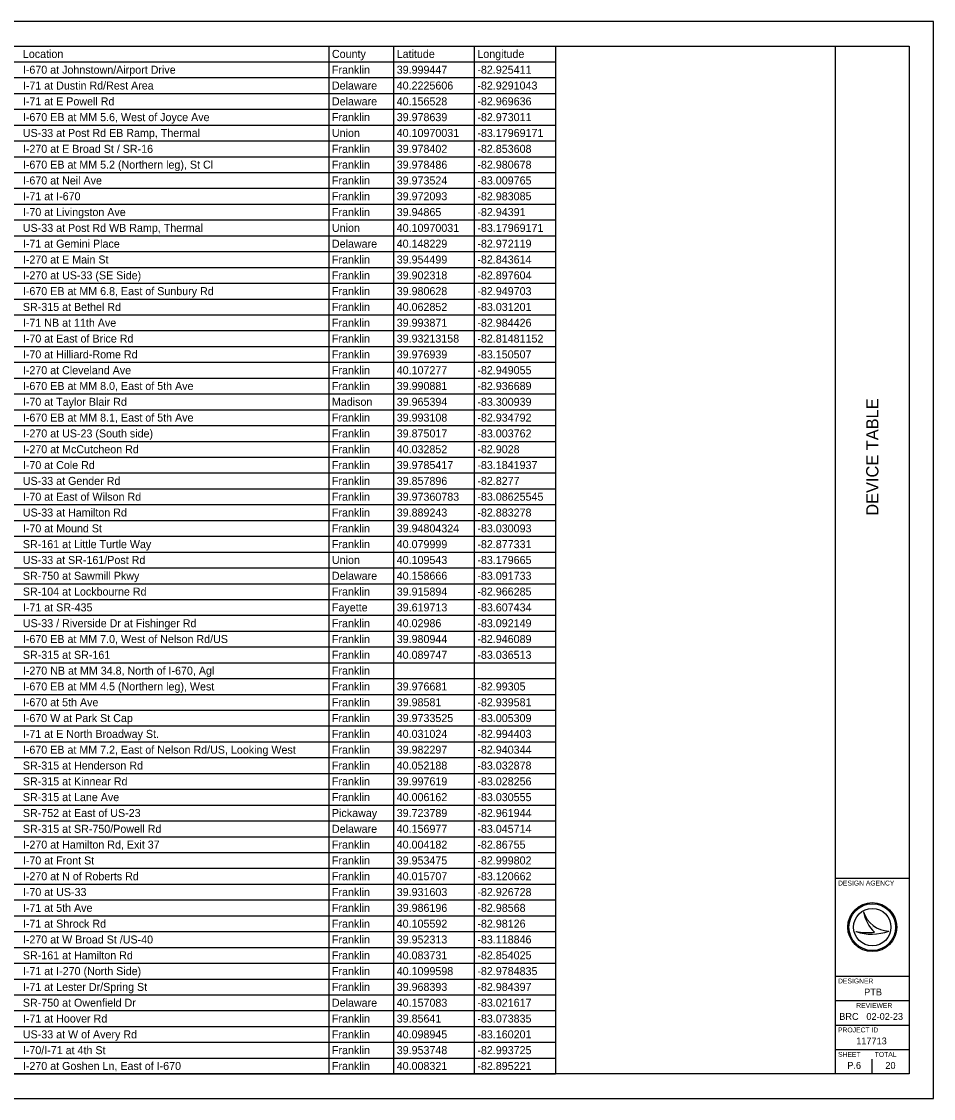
# Model space of a CAD drawing. Extents: x 0 to 34, y 0 to 22.
# Drawn here: x 15.36 to 34, y 0 to 22 of the extents above; entities that cross this region are included whole.
import ezdxf

# ---------------------------------------------------------------- set-up
doc = ezdxf.new("R2010")
doc.units = 0
for name, color, linetype in [('SH_Border', 7, 'Continuous'), ('SH_Cut_Line', 7, 'Continuous'), ('SH_Data', 7, 'Continuous'), ('SH_Text', 7, 'Continuous')]:
    doc.layers.add(name, color=color, linetype=linetype)

msp = doc.modelspace()

# ---------------------------------------------------------------- linework, layer by layer
at = {"layer": 'SH_Border'}
for p, q in [((32, 0.5), (32, 21.5)), ((32, 4.5), (33.5, 4.5)), ((32, 2.5), (33.5, 2.5)), ((32, 2), (33.5, 2)), ((32, 1.5), (33.5, 1.5)), ((32, 1), (33.5, 1))]:
    msp.add_line(p, q, dxfattribs=at)
msp.add_lwpolyline([(1.5, 21.5), (33.5, 21.5), (33.5, 0.5), (1.5, 0.5)], close=True, dxfattribs=at)
at = {"layer": 'SH_Cut_Line'}
msp.add_lwpolyline([(0, 0), (34, 0), (34, 22), (0, 22)], close=True, dxfattribs=at)
at = {"layer": 'SH_Data'}
for p, q in [((32.567, 3.81), (32.567, 3.81)), ((32.417, 3.41), (32.417, 3.41)), ((32.75, 3.5), (32.75, 3.5)), ((33.087, 3.419), (33.087, 3.419)), ((32.375, 0.675), (32.375, 0.675)), ((32.75, 0.5), (32.75, 0.8))]:
    msp.add_line(p, q, dxfattribs=at)
for radius in [0.5, 0.477, 0.477, 0.382]:
    msp.add_circle((32.75, 3.5), radius, dxfattribs=at)
for centre, radius, start, end in [((33.116, 3.998), 0.58, 198.9257, 198.9319), ((33.347, 3.97), 0.796, 191.6379, 191.6421), ((33.116, 3.998), 0.58, 198.9319, 267.1657), ((33.347, 3.97), 0.796, 191.6421, 226.0947), ((32.739, 4.37), 1.013, 251.4576, 290.0832), ((32.648, 4.654), 1.266, 259.4964, 259.4995), ((32.739, 4.37), 1.013, 251.4527, 251.4576), ((32.648, 4.654), 1.266, 259.4995, 276.6672)]:
    msp.add_arc(centre, radius, start, end, dxfattribs=at)
at = {"layer": 'SH_Text'}
for p, q in [((1.5, 21.5), (26.278, 21.5)), ((21.642, 21.5), (21.642, 0.502)), ((22.966, 21.5), (22.966, 0.502)), ((24.614, 21.5), (24.614, 0.502)), ((26.278, 21.5), (26.278, 0.502)), ((1.5, 21.177), (26.278, 21.177)), ((1.5, 20.854), (26.278, 20.854)), ((1.5, 20.531), (26.278, 20.531)), ((1.5, 20.208), (26.278, 20.208)), ((1.5, 19.885), (26.278, 19.885)), ((1.5, 19.562), (26.278, 19.562)), ((1.5, 19.239), (26.278, 19.239)), ((1.5, 18.916), (26.278, 18.916)), ((1.5, 18.593), (26.278, 18.593)), ((1.5, 18.27), (26.278, 18.27)), ((1.5, 17.946), (26.278, 17.946)), ((1.5, 17.623), (26.278, 17.623)), ((1.5, 17.3), (26.278, 17.3)), ((1.5, 16.977), (26.278, 16.977)), ((1.5, 16.654), (26.278, 16.654)), ((1.5, 16.331), (26.278, 16.331)), ((1.5, 16.008), (26.278, 16.008)), ((1.5, 15.685), (26.278, 15.685)), ((1.5, 15.362), (26.278, 15.362)), ((1.5, 15.039), (26.278, 15.039)), ((1.5, 14.716), (26.278, 14.716)), ((1.5, 14.393), (26.278, 14.393)), ((1.5, 14.07), (26.278, 14.07)), ((1.5, 13.747), (26.278, 13.747)), ((1.5, 13.424), (26.278, 13.424)), ((1.5, 13.101), (26.278, 13.101)), ((1.5, 12.778), (26.278, 12.778)), ((1.5, 12.455), (26.278, 12.455)), ((1.5, 12.132), (26.278, 12.132)), ((1.5, 11.809), (26.278, 11.809)), ((1.5, 11.486), (26.278, 11.486)), ((1.5, 11.162), (26.278, 11.162)), ((1.5, 10.839), (26.278, 10.839)), ((1.5, 10.516), (26.278, 10.516)), ((1.5, 10.193), (26.278, 10.193)), ((1.5, 9.87), (26.278, 9.87)), ((1.5, 9.547), (26.278, 9.547)), ((1.5, 9.224), (26.278, 9.224)), ((1.5, 8.901), (26.278, 8.901)), ((1.5, 8.578), (26.278, 8.578)), ((1.5, 8.255), (26.278, 8.255)), ((1.5, 7.932), (26.278, 7.932)), ((1.5, 7.609), (26.278, 7.609)), ((1.5, 7.286), (26.278, 7.286)), ((1.5, 6.963), (26.278, 6.963)), ((1.5, 6.64), (26.278, 6.64)), ((1.5, 6.317), (26.278, 6.317)), ((1.5, 5.994), (26.278, 5.994)), ((1.5, 5.671), (26.278, 5.671)), ((1.5, 5.348), (26.278, 5.348)), ((1.5, 5.025), (26.278, 5.025)), ((1.5, 4.702), (26.278, 4.702)), ((1.5, 4.379), (26.278, 4.379)), ((1.5, 4.055), (26.278, 4.055)), ((1.5, 3.732), (26.278, 3.732)), ((1.5, 3.409), (26.278, 3.409)), ((1.5, 3.086), (26.278, 3.086)), ((1.5, 2.763), (26.278, 2.763)), ((1.5, 2.44), (26.278, 2.44)), ((1.5, 2.117), (26.278, 2.117)), ((1.5, 1.794), (26.278, 1.794)), ((1.5, 1.471), (26.278, 1.471)), ((1.5, 1.148), (26.278, 1.148)), ((1.5, 0.825), (26.278, 0.825)), ((1.5, 0.502), (26.278, 0.502))]:
    msp.add_line(p, q, dxfattribs=at)

# ---------------------------------------------------------------- texts
at = {"layer": 'SH_Data'}
msp.add_text('DEVICE TABLE', height=0.25, rotation=90, dxfattribs=at).set_placement((32.875, 11.905))
for s, height, p in [('DESIGN AGENCY', 0.1, (32.05, 4.35)), ('DESIGNER', 0.1, (32.05, 2.35)), ('PTB', 0.14, (32.584, 2.105)), ('REVIEWER', 0.1, (32.422, 1.85)), ('BRC', 0.14, (32.075, 1.605)), ('02-02-23', 0.14, (32.629, 1.605)), ('PROJECT ID', 0.1, (32.05, 1.35)), ('117713', 0.14, (32.421, 1.105)), ('SHEET', 0.1, (32.05, 0.85)), ('TOTAL', 0.1, (32.8, 0.85)), ('P.6', 0.14, (32.239, 0.605)), ('20', 0.14, (33.017, 0.605))]:
    msp.add_text(s, height=height, dxfattribs=at).set_placement(p)
at = {"layer": 'SH_Text'}
for s, height, p in [('Location', 0.1635, (15.391, 21.257)), ('County', 0.1635, (21.707, 21.257)), ('Latitude', 0.1635, (23.031, 21.257)), ('Longitude', 0.1635, (24.679, 21.257)), ('I-670 at Johnstown/Airport Drive', 0.16346, (15.391, 20.934)), ('Franklin', 0.1635, (21.707, 20.934)), ('39.999447', 0.1635, (23.031, 20.934)), ('-82.925411', 0.1635, (24.679, 20.934)), ('I-71 at Dustin Rd/Rest Area', 0.16346, (15.391, 20.611)), ('Delaware', 0.1635, (21.707, 20.611)), ('40.2225606', 0.1635, (23.031, 20.611)), ('-82.9291043', 0.16346, (24.679, 20.611)), ('I-71 at E Powell Rd', 0.16346, (15.391, 20.288)), ('Delaware', 0.1635, (21.707, 20.288)), ('40.156528', 0.1635, (23.031, 20.288)), ('-82.969636', 0.1635, (24.679, 20.288)), ('I-670 EB at MM 5.6, West of Joyce Ave', 0.16346, (15.391, 19.965)), ('Franklin', 0.1635, (21.707, 19.965)), ('39.978639', 0.1635, (23.031, 19.965)), ('-82.973011', 0.1635, (24.679, 19.965)), ('US-33 at Post Rd EB Ramp, Thermal', 0.16346, (15.391, 19.642)), ('Union', 0.1635, (21.707, 19.642)), ('40.10970031', 0.16346, (23.031, 19.642)), ('-83.17969171', 0.16346, (24.679, 19.642)), ('I-270 at E Broad St / SR-16', 0.16346, (15.391, 19.318)), ('Franklin', 0.1635, (21.707, 19.318)), ('39.978402', 0.1635, (23.031, 19.318)), ('-82.853608', 0.1635, (24.679, 19.318)), ('I-670 EB at MM 5.2 (Northern leg), St Cl', 0.16346, (15.391, 18.995)), ('Franklin', 0.1635, (21.707, 18.995)), ('39.978486', 0.1635, (23.031, 18.995)), ('-82.980678', 0.1635, (24.679, 18.995)), ('I-670 at Neil Ave', 0.16346, (15.391, 18.672)), ('Franklin', 0.1635, (21.707, 18.672)), ('39.973524', 0.1635, (23.031, 18.672)), ('-83.009765', 0.1635, (24.679, 18.672)), ('I-71 at I-670', 0.16346, (15.391, 18.349)), ('Franklin', 0.1635, (21.707, 18.349)), ('39.972093', 0.1635, (23.031, 18.349)), ('-82.983085', 0.1635, (24.679, 18.349)), ('I-70 at Livingston Ave', 0.16346, (15.391, 18.026)), ('Franklin', 0.1635, (21.707, 18.026)), ('39.94865', 0.1635, (23.031, 18.026)), ('-82.94391', 0.1635, (24.679, 18.026)), ('US-33 at Post Rd WB Ramp, Thermal', 0.16346, (15.391, 17.703)), ('Union', 0.1635, (21.707, 17.703)), ('40.10970031', 0.16346, (23.031, 17.703)), ('-83.17969171', 0.16346, (24.679, 17.703)), ('I-71 at Gemini Place', 0.16346, (15.391, 17.38)), ('Delaware', 0.1635, (21.707, 17.38)), ('40.148229', 0.1635, (23.031, 17.38)), ('-82.972119', 0.1635, (24.679, 17.38)), ('I-270 at E Main St', 0.16346, (15.391, 17.057)), ('Franklin', 0.1635, (21.707, 17.057)), ('39.954499', 0.1635, (23.031, 17.057)), ('-82.843614', 0.1635, (24.679, 17.057)), ('I-270 at US-33 (SE Side)', 0.16346, (15.391, 16.734)), ('Franklin', 0.1635, (21.707, 16.734)), ('39.902318', 0.1635, (23.031, 16.734)), ('-82.897604', 0.1635, (24.679, 16.734)), ('I-670 EB at MM 6.8, East of Sunbury Rd', 0.16346, (15.391, 16.411)), ('Franklin', 0.1635, (21.707, 16.411)), ('39.980628', 0.1635, (23.031, 16.411)), ('-82.949703', 0.1635, (24.679, 16.411)), ('SR-315 at Bethel Rd', 0.16346, (15.391, 16.088)), ('Franklin', 0.1635, (21.707, 16.088)), ('40.062852', 0.1635, (23.031, 16.088)), ('-83.031201', 0.1635, (24.679, 16.088)), ('I-71 NB at 11th Ave', 0.16346, (15.391, 15.765)), ('Franklin', 0.1635, (21.707, 15.765)), ('39.993871', 0.1635, (23.031, 15.765)), ('-82.984426', 0.1635, (24.679, 15.765)), ('I-70 at East of Brice Rd', 0.16346, (15.391, 15.442)), ('Franklin', 0.1635, (21.707, 15.442)), ('39.93213158', 0.16346, (23.031, 15.442)), ('-82.81481152', 0.16346, (24.679, 15.442)), ('I-70 at Hilliard-Rome Rd', 0.16346, (15.391, 15.119)), ('Franklin', 0.1635, (21.707, 15.119)), ('39.976939', 0.1635, (23.031, 15.119)), ('-83.150507', 0.1635, (24.679, 15.119)), ('I-270 at Cleveland Ave', 0.16346, (15.391, 14.796)), ('Franklin', 0.1635, (21.707, 14.796)), ('40.107277', 0.1635, (23.031, 14.796)), ('-82.949055', 0.1635, (24.679, 14.796)), ('I-670 EB at MM 8.0, East of 5th Ave', 0.16346, (15.391, 14.473)), ('Franklin', 0.1635, (21.707, 14.473)), ('39.990881', 0.1635, (23.031, 14.473)), ('-82.936689', 0.1635, (24.679, 14.473)), ('I-70 at Taylor Blair Rd', 0.16346, (15.391, 14.15)), ('Madison', 0.1635, (21.707, 14.15)), ('39.965394', 0.1635, (23.031, 14.15)), ('-83.300939', 0.1635, (24.679, 14.15)), ('I-670 EB at MM 8.1, East of 5th Ave', 0.16346, (15.391, 13.827)), ('Franklin', 0.1635, (21.707, 13.827)), ('39.993108', 0.1635, (23.031, 13.827)), ('-82.934792', 0.1635, (24.679, 13.827)), ('I-270 at US-23 (South side)', 0.16346, (15.391, 13.504)), ('Franklin', 0.1635, (21.707, 13.504)), ('39.875017', 0.1635, (23.031, 13.504)), ('-83.003762', 0.1635, (24.679, 13.504)), ('I-270 at McCutcheon Rd', 0.16346, (15.391, 13.181)), ('Franklin', 0.1635, (21.707, 13.181)), ('40.032852', 0.1635, (23.031, 13.181)), ('-82.9028', 0.1635, (24.679, 13.181)), ('I-70 at Cole Rd', 0.16346, (15.391, 12.858)), ('Franklin', 0.1635, (21.707, 12.858)), ('39.9785417', 0.1635, (23.031, 12.858)), ('-83.1841937', 0.16346, (24.679, 12.858)), ('US-33 at Gender Rd', 0.16346, (15.391, 12.534)), ('Franklin', 0.1635, (21.707, 12.534)), ('39.857896', 0.1635, (23.031, 12.534)), ('-82.8277', 0.1635, (24.679, 12.534)), ('I-70 at East of Wilson Rd', 0.16346, (15.391, 12.211)), ('Franklin', 0.1635, (21.707, 12.211)), ('39.97360783', 0.16346, (23.031, 12.211)), ('-83.08625545', 0.16346, (24.679, 12.211)), ('US-33 at Hamilton Rd', 0.16346, (15.391, 11.888)), ('Franklin', 0.1635, (21.707, 11.888)), ('39.889243', 0.1635, (23.031, 11.888)), ('-82.883278', 0.1635, (24.679, 11.888)), ('I-70 at Mound St', 0.16346, (15.391, 11.565)), ('Franklin', 0.1635, (21.707, 11.565)), ('39.94804324', 0.16346, (23.031, 11.565)), ('-83.030093', 0.1635, (24.679, 11.565)), ('SR-161 at Little Turtle Way', 0.16346, (15.391, 11.242)), ('Franklin', 0.1635, (21.707, 11.242)), ('40.079999', 0.1635, (23.031, 11.242)), ('-82.877331', 0.1635, (24.679, 11.242)), ('US-33 at SR-161/Post Rd', 0.16346, (15.391, 10.919)), ('Union', 0.1635, (21.707, 10.919)), ('40.109543', 0.1635, (23.031, 10.919)), ('-83.179665', 0.1635, (24.679, 10.919)), ('SR-750 at Sawmill Pkwy', 0.16346, (15.391, 10.596)), ('Delaware', 0.1635, (21.707, 10.596)), ('40.158666', 0.1635, (23.031, 10.596)), ('-83.091733', 0.1635, (24.679, 10.596)), ('SR-104 at Lockbourne Rd', 0.16346, (15.391, 10.273)), ('Franklin', 0.1635, (21.707, 10.273)), ('39.915894', 0.1635, (23.031, 10.273)), ('-82.966285', 0.1635, (24.679, 10.273)), ('I-71 at SR-435', 0.16346, (15.391, 9.95)), ('Fayette', 0.1635, (21.707, 9.95)), ('39.619713', 0.1635, (23.031, 9.95)), ('-83.607434', 0.1635, (24.679, 9.95)), ('US-33 / Riverside Dr at Fishinger Rd', 0.16346, (15.391, 9.627)), ('Franklin', 0.1635, (21.707, 9.627)), ('40.02986', 0.1635, (23.031, 9.627)), ('-83.092149', 0.1635, (24.679, 9.627)), ('I-670 EB at MM 7.0, West of Nelson Rd/US', 0.16346, (15.391, 9.304)), ('Franklin', 0.1635, (21.707, 9.304)), ('39.980944', 0.1635, (23.031, 9.304)), ('-82.946089', 0.1635, (24.679, 9.304)), ('SR-315 at SR-161', 0.16346, (15.391, 8.981)), ('Franklin', 0.1635, (21.707, 8.981)), ('40.089747', 0.1635, (23.031, 8.981)), ('-83.036513', 0.1635, (24.679, 8.981)), ('I-270 NB at MM 34.8, North of I-670, Agl', 0.16346, (15.391, 8.658)), ('Franklin', 0.1635, (21.707, 8.658)), ('I-670 EB at MM 4.5 (Northern leg), West', 0.16346, (15.391, 8.335)), ('Franklin', 0.1635, (21.707, 8.335)), ('39.976681', 0.1635, (23.031, 8.335)), ('-82.99305', 0.1635, (24.679, 8.335)), ('I-670 at 5th Ave', 0.16346, (15.391, 8.012)), ('Franklin', 0.1635, (21.707, 8.012)), ('39.98581', 0.1635, (23.031, 8.012)), ('-82.939581', 0.1635, (24.679, 8.012)), ('I-670 W at Park St Cap', 0.16346, (15.391, 7.689)), ('Franklin', 0.1635, (21.707, 7.689)), ('39.9733525', 0.1635, (23.031, 7.689)), ('-83.005309', 0.1635, (24.679, 7.689)), ('I-71 at E North Broadway St.', 0.16346, (15.391, 7.366)), ('Franklin', 0.1635, (21.707, 7.366)), ('40.031024', 0.1635, (23.031, 7.366)), ('-82.994403', 0.1635, (24.679, 7.366)), ('I-670 EB at MM 7.2, East of Nelson Rd/US, Looking West', 0.16346, (15.391, 7.043)), ('Franklin', 0.1635, (21.707, 7.043)), ('39.982297', 0.1635, (23.031, 7.043)), ('-82.940344', 0.1635, (24.679, 7.043)), ('SR-315 at Henderson Rd', 0.16346, (15.391, 6.72)), ('Franklin', 0.1635, (21.707, 6.72)), ('40.052188', 0.1635, (23.031, 6.72)), ('-83.032878', 0.1635, (24.679, 6.72)), ('SR-315 at Kinnear Rd', 0.16346, (15.391, 6.397)), ('Franklin', 0.1635, (21.707, 6.397)), ('39.997619', 0.1635, (23.031, 6.397)), ('-83.028256', 0.1635, (24.679, 6.397)), ('SR-315 at Lane Ave', 0.16346, (15.391, 6.074)), ('Franklin', 0.1635, (21.707, 6.074)), ('40.006162', 0.1635, (23.031, 6.074)), ('-83.030555', 0.1635, (24.679, 6.074)), ('SR-752 at East of US-23', 0.16346, (15.391, 5.75)), ('Pickaway', 0.1635, (21.707, 5.75)), ('39.723789', 0.1635, (23.031, 5.75)), ('-82.961944', 0.1635, (24.679, 5.75)), ('SR-315 at SR-750/Powell Rd', 0.16346, (15.391, 5.427)), ('Delaware', 0.1635, (21.707, 5.427)), ('40.156977', 0.1635, (23.031, 5.427)), ('-83.045714', 0.1635, (24.679, 5.427)), ('I-270 at Hamilton Rd, Exit 37', 0.16346, (15.391, 5.104)), ('Franklin', 0.1635, (21.707, 5.104)), ('40.004182', 0.1635, (23.031, 5.104)), ('-82.86755', 0.1635, (24.679, 5.104)), ('I-70 at Front St', 0.16346, (15.391, 4.781)), ('Franklin', 0.1635, (21.707, 4.781)), ('39.953475', 0.1635, (23.031, 4.781)), ('-82.999802', 0.1635, (24.679, 4.781)), ('I-270 at N of Roberts Rd', 0.16346, (15.391, 4.458)), ('Franklin', 0.1635, (21.707, 4.458)), ('40.015707', 0.1635, (23.031, 4.458)), ('-83.120662', 0.1635, (24.679, 4.458)), ('I-70 at US-33', 0.16346, (15.391, 4.135)), ('Franklin', 0.1635, (21.707, 4.135)), ('39.931603', 0.1635, (23.031, 4.135)), ('-82.926728', 0.1635, (24.679, 4.135)), ('I-71 at 5th Ave', 0.16346, (15.391, 3.812)), ('Franklin', 0.1635, (21.707, 3.812)), ('39.986196', 0.1635, (23.031, 3.812)), ('-82.98568', 0.1635, (24.679, 3.812)), ('I-71 at Shrock Rd', 0.16346, (15.391, 3.489)), ('Franklin', 0.1635, (21.707, 3.489)), ('40.105592', 0.1635, (23.031, 3.489)), ('-82.98126', 0.1635, (24.679, 3.489)), ('I-270 at W Broad St /US-40', 0.16346, (15.391, 3.166)), ('Franklin', 0.1635, (21.707, 3.166)), ('39.952313', 0.1635, (23.031, 3.166)), ('-83.118846', 0.1635, (24.679, 3.166)), ('SR-161 at Hamilton Rd', 0.16346, (15.391, 2.843)), ('Franklin', 0.1635, (21.707, 2.843)), ('40.083731', 0.1635, (23.031, 2.843)), ('-82.854025', 0.1635, (24.679, 2.843)), ('I-71 at I-270 (North Side)', 0.16346, (15.391, 2.52)), ('Franklin', 0.1635, (21.707, 2.52)), ('40.1099598', 0.1635, (23.031, 2.52)), ('-82.9784835', 0.16346, (24.679, 2.52)), ('I-71 at Lester Dr/Spring St', 0.16346, (15.391, 2.197)), ('Franklin', 0.1635, (21.707, 2.197)), ('39.968393', 0.1635, (23.031, 2.197)), ('-82.984397', 0.1635, (24.679, 2.197)), ('SR-750 at Owenfield Dr', 0.16346, (15.391, 1.874)), ('Delaware', 0.1635, (21.707, 1.874)), ('40.157083', 0.1635, (23.031, 1.874)), ('-83.021617', 0.1635, (24.679, 1.874)), ('I-71 at Hoover Rd', 0.16346, (15.391, 1.551)), ('Franklin', 0.1635, (21.707, 1.551)), ('39.85641', 0.1635, (23.031, 1.551)), ('-83.073835', 0.1635, (24.679, 1.551)), ('US-33 at W of Avery Rd', 0.16346, (15.391, 1.228)), ('Franklin', 0.1635, (21.707, 1.228)), ('40.098945', 0.1635, (23.031, 1.228)), ('-83.160201', 0.1635, (24.679, 1.228)), ('I-70/I-71 at 4th St', 0.16346, (15.391, 0.905)), ('Franklin', 0.1635, (21.707, 0.905)), ('39.953748', 0.1635, (23.031, 0.905)), ('-82.993725', 0.1635, (24.679, 0.905)), ('I-270 at Goshen Ln, East of I-670', 0.16346, (15.391, 0.582)), ('Franklin', 0.1635, (21.707, 0.582)), ('40.008321', 0.1635, (23.031, 0.582)), ('-82.895221', 0.1635, (24.679, 0.582))]:
    msp.add_text(s, height=height, dxfattribs=at).set_placement(p)

doc.saveas('drawing.dxf')
